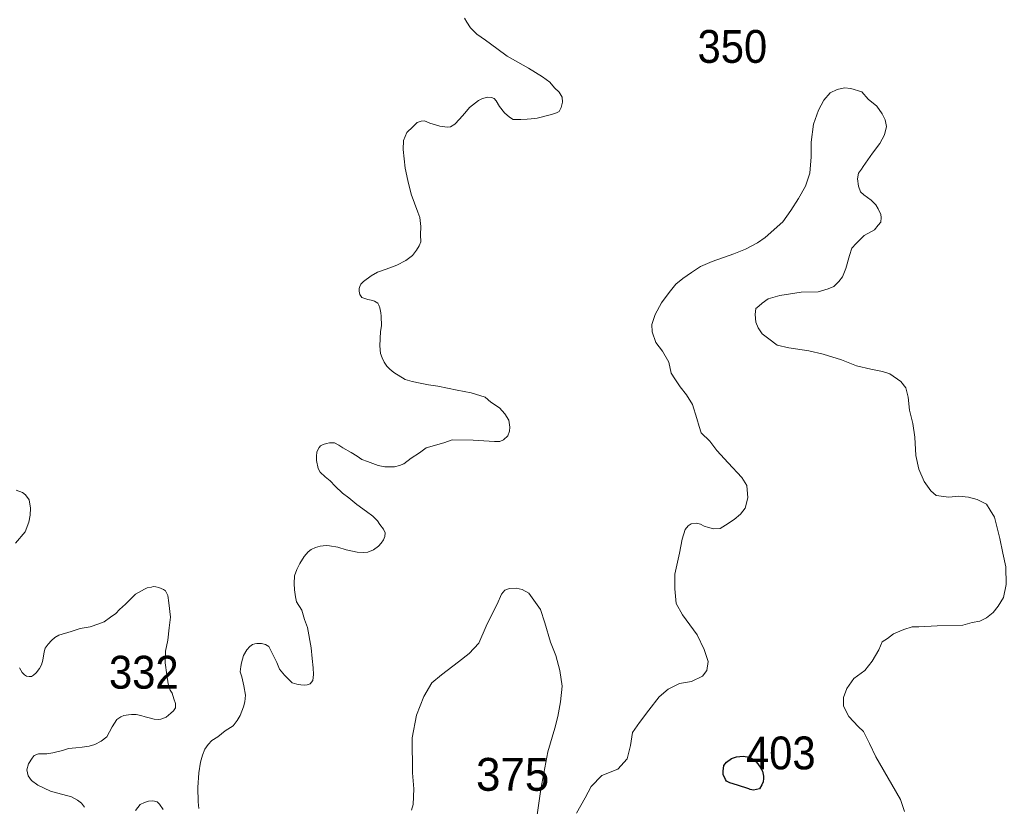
# Model space of a CAD drawing. Extents: x 445.4 to 500, y 8728.7 to 8784.
# Drawn here: x 477.878 to 482.683, y 8738.808 to 8742.638 of the extents above; entities that cross this region are included whole.
import ezdxf

# ---------------------------------------------------------------- set-up
doc = ezdxf.new("R2010")
doc.units = 0
doc.header["$LTSCALE"] = 0.064
doc.layers.add('1', color=7, linetype='Continuous', lineweight=25)
doc.layers.add('2', color=7, linetype='Continuous', lineweight=13)
doc.layers.add('21', color=7, linetype='Continuous')

msp = doc.modelspace()

# ---------------------------------------------------------------- linework, layer by layer
at = {"layer": '1'}
msp.add_lwpolyline([(481.4291, 8738.8939), (481.3733, 8738.9113), (481.3373, 8738.9218), (481.321, 8738.9311), (481.3152, 8738.938), (481.3035, 8738.9624), (481.3035, 8738.9798), (481.3082, 8739.0065), (481.3198, 8739.0239), (481.3454, 8739.0413), (481.3687, 8739.0494), (481.4012, 8739.0529), (481.4326, 8739.0471), (481.4501, 8739.0378), (481.4629, 8739.0262), (481.4733, 8739.0146), (481.4884, 8738.9937), (481.4966, 8738.9786), (481.5012, 8738.9543), (481.5001, 8738.9438), (481.4989, 8738.9276), (481.4931, 8738.9136), (481.4815, 8738.8939), (481.4664, 8738.8893), (481.4524, 8738.887), (481.435, 8738.8893)], close=True, dxfattribs=at)
at = {"layer": '2'}
for points in [[(480.0452, 8742.6452), (480.0558, 8742.6256), (480.0739, 8742.5985), (480.1042, 8742.5683), (480.1465, 8742.5381), (480.2024, 8742.4974), (480.2523, 8742.4612), (480.3568, 8742.4029), (480.4248, 8742.3592), (480.4596, 8742.3336), (480.4823, 8742.3064), (480.5049, 8742.2853), (480.52, 8742.2612), (480.5215, 8742.237), (480.5155, 8742.2099), (480.5049, 8742.1918), (480.4928, 8742.1842), (480.4687, 8742.1767)], [(481.0917, 8739.4061), (481.1496, 8739.4163), (481.2044, 8739.4419), (481.2249, 8739.4691), (481.2317, 8739.5133), (481.2112, 8739.571), (481.1772, 8739.6424), (481.1057, 8739.741), (481.075, 8739.7954), (481.0682, 8739.8667), (481.0682, 8739.9381), (481.092, 8740.0401), (481.1054, 8740.1093), (481.1189, 8740.1554), (481.1343, 8740.1746), (481.1478, 8740.1842), (481.1728, 8740.1861), (481.1939, 8740.1823), (481.2113, 8740.1727), (481.2324, 8740.165), (481.2594, 8740.1592), (481.2901, 8740.1611), (481.3152, 8740.1765), (481.3575, 8740.2053), (481.3883, 8740.2303), (481.4114, 8740.2591), (481.4248, 8740.3109), (481.419, 8740.3705), (481.396, 8740.4089), (481.3286, 8740.4799), (481.2728, 8740.5414), (481.2401, 8740.5855), (481.1975, 8740.627), (481.1871, 8740.6568), (481.1753, 8740.6967), (481.1542, 8740.7647), (481.126, 8740.8116), (481.0954, 8740.8514), (481.0696, 8740.8889), (481.0508, 8740.9171), (481.0391, 8740.971), (481.0085, 8741.0245), (480.9756, 8741.0667), (480.9591, 8741.1183), (480.9568, 8741.1534), (480.9732, 8741.2027), (481.0038, 8741.259), (481.0414, 8741.3105), (481.0743, 8741.3504), (481.1072, 8741.3785), (481.1494, 8741.4067), (481.1941, 8741.4372), (481.2505, 8741.4606), (481.3562, 8741.4981), (481.4125, 8741.5216), (481.4713, 8741.552), (481.5089, 8741.5778), (481.5942, 8741.6546), (481.6341, 8741.7085), (481.6717, 8741.7671), (481.7046, 8741.8281), (481.7257, 8741.8914), (481.7328, 8741.9711), (481.7328, 8742.0414), (481.745, 8742.1298), (481.7685, 8742.1978), (481.7943, 8742.2471), (481.8248, 8742.2822), (481.8601, 8742.2986), (481.8953, 8742.3057), (481.9259, 8742.3033), (481.9799, 8742.2869), (482.0104, 8742.2517), (482.0527, 8742.2166), (482.0786, 8742.1791), (482.0926, 8742.1509), (482.0997, 8742.1181), (482.0903, 8742.0782), (482.0668, 8742.036), (482.0316, 8741.9891), (481.9869, 8741.9235), (481.9776, 8741.9103), (481.9635, 8741.8916), (481.9588, 8741.8635), (481.9635, 8741.8283), (481.9729, 8741.8001), (481.9893, 8741.7861), (482.0246, 8741.7603), (482.0481, 8741.7368), (482.0598, 8741.7181), (482.0716, 8741.6899), (482.0739, 8741.6759), (482.0716, 8741.6524), (482.0598, 8741.6384), (482.041, 8741.6149), (481.9917, 8741.5868), (481.9517, 8741.5493), (481.9306, 8741.5258), (481.9189, 8741.4906), (481.9024, 8741.426), (481.886, 8741.3861)], [(480.4687, 8742.1767), (480.3988, 8742.1595), (480.37, 8742.155), (480.3504, 8742.1535), (480.3187, 8742.152), (480.2809, 8742.152), (480.2643, 8742.164), (480.2386, 8742.1851), (480.2144, 8742.2153), (480.1993, 8742.2424), (480.1887, 8742.2545), (480.1766, 8742.259), (480.1585, 8742.2605), (480.1328, 8742.2545), (480.1132, 8742.244), (480.0693, 8742.2108), (480.0467, 8742.1836), (480.0195, 8742.1535), (479.9968, 8742.1293), (479.9756, 8742.1173), (479.9605, 8742.1142), (479.9243, 8742.1203), (479.8759, 8742.1339), (479.8502, 8742.1459), (479.8336, 8742.1444), (479.814, 8742.1384), (479.7928, 8742.1173), (479.7641, 8742.0886), (479.7475, 8742.0494), (479.746, 8742.0057), (479.7548, 8741.9161), (479.7684, 8741.8558), (479.785, 8741.7894), (479.818, 8741.7013), (479.8263, 8741.6745), (479.8312, 8741.6316), (479.83, 8741.59), (479.8312, 8741.5569), (479.8239, 8741.5373), (479.8104, 8741.5165), (479.7907, 8741.4908), (479.7588, 8741.4651), (479.7147, 8741.4431), (479.6628, 8741.4238), (479.6211, 8741.4092), (479.5892, 8741.3908), (479.5524, 8741.3639), (479.5389, 8741.3504), (479.5353, 8741.3397), (479.5311, 8741.3288), (479.5311, 8741.317), (479.5344, 8741.2994), (479.5453, 8741.286), (479.5537, 8741.2818), (479.5731, 8741.2759), (479.5899, 8741.2734), (479.6067, 8741.2684), (479.6151, 8741.2634), (479.6218, 8741.2575), (479.6268, 8741.2483), (479.6319, 8741.2357), (479.6369, 8741.2114), (479.6394, 8741.1946), (479.6409, 8741.1477), (479.6362, 8741.1194), (479.6327, 8741.0508), (479.635, 8741.013), (479.6433, 8740.9917), (479.654, 8740.9704), (479.6658, 8740.9515), (479.6812, 8740.9373), (479.7002, 8740.9208), (479.7549, 8740.887), (479.7892, 8740.8764), (479.8283, 8740.8681), (479.8698, 8740.861), (479.9148, 8740.8539), (479.961, 8740.8445), (480.0083, 8740.835), (480.0774, 8740.8207), (480.1449, 8740.8007), (480.1722, 8740.7752), (480.2142, 8740.7479), (480.2415, 8740.7187), (480.2598, 8740.6878), (480.2653, 8740.655), (480.2634, 8740.635), (480.2561, 8740.6113), (480.2343, 8740.5931), (480.216, 8740.584), (480.1905, 8740.584), (480.0865, 8740.5913), (479.9844, 8740.5931), (479.9442, 8740.5786), (479.8585, 8740.5531), (479.8257, 8740.5294), (479.7855, 8740.5039), (479.749, 8740.4761), (479.7285, 8740.4679), (479.7029, 8740.4617), (479.6803, 8740.4607)], [(481.886, 8741.3861), (481.8672, 8741.3627), (481.8437, 8741.3392), (481.8155, 8741.3275), (481.7662, 8741.3134), (481.6839, 8741.3111), (481.5806, 8741.2947), (481.5242, 8741.2783), (481.4936, 8741.2572), (481.4772, 8741.2431), (481.4631, 8741.2314), (481.4608, 8741.2032), (481.4631, 8741.1657), (481.4749, 8741.1376), (481.4936, 8741.1094), (481.5265, 8741.0837), (481.5665, 8741.0532), (481.6248, 8741.04), (481.7211, 8741.0259), (481.7916, 8741.0095), (481.8809, 8740.9814), (481.9537, 8740.9532), (482.0242, 8740.9368), (482.0806, 8740.9251), (482.1158, 8740.9134), (482.1698, 8740.8759), (482.1933, 8740.8454), (482.2051, 8740.8008), (482.2121, 8740.7375), (482.2286, 8740.6719), (482.238, 8740.6062), (482.2433, 8740.5156), (482.2574, 8740.4499), (482.2833, 8740.389), (482.3161, 8740.3444), (482.342, 8740.321), (482.4031, 8740.3139), (482.4524, 8740.3186), (482.4994, 8740.3139), (482.5417, 8740.3022), (482.5863, 8740.2788), (482.6051, 8740.2506), (482.6262, 8740.2155), (482.6521, 8740.1123), (482.6666, 8740.0403), (482.6807, 8739.9747), (482.6831, 8739.8879), (482.669, 8739.8246), (482.6431, 8739.7824), (482.6196, 8739.7519), (482.5868, 8739.7262), (482.5539, 8739.7097), (482.5163, 8739.7027), (482.4716, 8739.691), (482.3471, 8739.6863), (482.2579, 8739.6816), (482.225, 8739.6816), (482.185, 8739.6699), (482.1334, 8739.6488), (482.1052, 8739.6253), (482.0793, 8739.6089), (482.0622, 8739.5696), (482.0293, 8739.5156), (481.994, 8739.4687), (481.94, 8739.4312), (481.9071, 8739.382), (481.8907, 8739.3374), (481.8907, 8739.2952), (481.9165, 8739.246), (481.9612, 8739.1968), (481.987, 8739.1733), (482.0175, 8739.1147), (482.0481, 8739.049), (482.1259, 8738.9139), (482.1682, 8738.8412), (482.187, 8738.7826)], [(479.6803, 8740.4607), (479.6567, 8740.4617), (479.6239, 8740.4679), (479.5716, 8740.4863), (479.5449, 8740.4976), (479.5214, 8740.5129), (479.4926, 8740.5303), (479.4516, 8740.5529), (479.4331, 8740.5672), (479.4106, 8740.5774), (479.387, 8740.5774), (479.3726, 8740.5744), (479.3562, 8740.5703), (479.3439, 8740.5631), (479.3367, 8740.5549), (479.3296, 8740.5447), (479.3254, 8740.5324), (479.3234, 8740.5129), (479.3244, 8740.4925), (479.3316, 8740.4536), (479.3419, 8740.4351), (479.3654, 8740.4126), (479.3901, 8740.3932), (479.4146, 8740.3669), (479.4505, 8740.3331), (479.4813, 8740.3095), (479.5203, 8740.2778), (479.5669, 8740.2434), (479.598, 8740.221), (479.6204, 8740.1986), (479.6324, 8740.1797), (479.6497, 8740.1573), (479.6583, 8740.1401), (479.6566, 8740.1212), (479.6497, 8740.1057), (479.6393, 8740.0902), (479.6255, 8740.0748), (479.6014, 8740.0575), (479.5738, 8740.0455), (479.5514, 8740.0438), (479.5221, 8740.0455), (479.4687, 8740.0575), (479.4273, 8740.0696), (479.3876, 8740.0765), (479.3704, 8740.0782), (479.3411, 8740.0748), (479.3187, 8740.0679), (479.298, 8740.0593), (479.2825, 8740.0472), (479.2635, 8740.0249), (479.2428, 8739.9904), (479.2273, 8739.9612), (479.217, 8739.9302), (479.2152, 8739.8924), (479.2166, 8739.8624), (479.2217, 8739.828), (479.2269, 8739.8039), (479.2528, 8739.7626), (479.2648, 8739.7178), (479.2803, 8739.6783), (479.2976, 8739.5795), (479.3028, 8739.5279), (479.308, 8739.4831), (479.3096, 8739.45), (479.3061, 8739.4207), (479.2923, 8739.4052), (479.2785, 8739.4001), (479.2647, 8739.3984), (479.2475, 8739.4001), (479.2285, 8739.4035), (479.2044, 8739.4087), (479.1682, 8739.4465), (479.1441, 8739.4758), (479.1303, 8739.5085), (479.0923, 8739.5859), (479.0751, 8739.5962), (479.0561, 8739.6014), (479.0337, 8739.6014), (479.0234, 8739.5997), (479.0113, 8739.5962), (478.9993, 8739.5859), (478.9837, 8739.5704), (478.9682, 8739.5429), (478.9579, 8739.5068), (478.9544, 8739.4896), (478.9527, 8739.4637), (478.9596, 8739.4379), (478.9699, 8739.3949), (478.9786, 8739.3502), (478.9751, 8739.3175), (478.9682, 8739.2934), (478.9524, 8739.2497), (478.9369, 8739.2256), (478.918, 8739.1998), (478.8783, 8739.1757), (478.8438, 8739.1465), (478.8145, 8739.1293), (478.7953, 8739.1095), (478.7798, 8739.0871), (478.7677, 8739.0579), (478.7591, 8739.0235)], [(477.8573, 8740.0899), (477.9046, 8740.1447), (477.9226, 8740.1919), (477.9294, 8740.2256), (477.9316, 8740.2594), (477.9249, 8740.2998), (477.9068, 8740.3245), (477.8911, 8740.3358), (477.8618, 8740.347)], [(478.6365, 8739.309), (478.6293, 8739.3319), (478.6207, 8739.3591), (478.6106, 8739.3735), (478.6009, 8739.4045), (478.595, 8739.4477), (478.5872, 8739.5066), (478.5891, 8739.5635), (478.599, 8739.6165), (478.6068, 8739.6774), (478.6127, 8739.7284), (478.6049, 8739.7991), (478.5989, 8739.834), (478.5932, 8739.8482), (478.5882, 8739.8574), (478.579, 8739.8638), (478.5669, 8739.8694), (478.5555, 8739.8744), (478.5413, 8739.8765), (478.5279, 8739.8779), (478.5193, 8739.8758), (478.4995, 8739.8715), (478.4867, 8739.8659), (478.4427, 8739.8411), (478.4221, 8739.8212), (478.3937, 8739.7922), (478.3646, 8739.7667), (478.3461, 8739.7475), (478.3198, 8739.7298), (478.2893, 8739.7057), (478.2639, 8739.6966), (478.2208, 8739.6829), (478.1729, 8739.6747), (478.129, 8739.6601), (478.0696, 8739.6423), (478.0501, 8739.6309), (478.0338, 8739.6155), (478.0167, 8739.5984), (478.0029, 8739.579), (477.998, 8739.5611), (477.9915, 8739.5205), (477.985, 8739.4978), (477.9743, 8739.4786), (477.958, 8739.4583), (477.945, 8739.4462), (477.936, 8739.4405), (477.9239, 8739.4405), (477.9117, 8739.4413), (477.9011, 8739.4478), (477.8905, 8739.4592), (477.8775, 8739.4827)], [(479.787, 8738.7891), (479.7939, 8738.8167), (479.7985, 8738.8928), (479.7916, 8738.9711), (479.7904, 8739.1417), (479.8101, 8739.252), (479.8457, 8739.3426), (479.8852, 8739.4096), (479.9325, 8739.449), (480.0154, 8739.5121), (480.0668, 8739.5515), (480.1141, 8739.6027), (480.1497, 8739.6855), (480.1787, 8739.7457), (480.2033, 8739.7928), (480.2241, 8739.8419), (480.2411, 8739.8607), (480.2638, 8739.8683), (480.2959, 8739.8701), (480.3261, 8739.8645), (480.3583, 8739.8456), (480.3828, 8739.8117), (480.415, 8739.7664), (480.4357, 8739.7023), (480.4641, 8739.608), (480.4887, 8739.542), (480.5094, 8739.4703), (480.5209, 8739.394), (480.5115, 8739.3167), (480.4983, 8739.245), (480.485, 8739.1884), (480.4502, 8739.0741), (480.4156, 8738.8911), (480.381, 8738.6426)], [(480.5906, 8738.7754), (480.6315, 8738.8502), (480.6621, 8738.9046), (480.7132, 8738.9589), (480.7915, 8738.9895), (480.8363, 8739.039), (480.8533, 8739.1036), (480.8635, 8739.1682), (480.8976, 8739.2158), (480.9419, 8739.277), (480.9929, 8739.3415), (481.0372, 8739.3789), (481.0917, 8739.4061)], [(478.1931, 8738.804), (478.1793, 8738.8229), (478.1592, 8738.8384), (478.1297, 8738.8541), (478.0884, 8738.8659), (478.0569, 8738.8737), (478.0274, 8738.8816), (477.9979, 8738.8973), (477.9665, 8738.911), (477.935, 8738.9346), (477.9193, 8738.9562), (477.9134, 8738.9856), (477.9213, 8739.0151), (477.939, 8739.0425), (477.9488, 8739.0563), (477.9704, 8739.0641), (478.0097, 8739.0641), (478.0392, 8739.068), (478.0864, 8739.0798), (478.1159, 8739.0896), (478.1513, 8739.0936), (478.1828, 8739.0955), (478.2162, 8739.1014), (478.2437, 8739.1093), (478.2752, 8739.125), (478.3027, 8739.1465), (478.3283, 8739.1956), (478.3508, 8739.2302), (478.3709, 8739.2431), (478.3853, 8739.2503), (478.4082, 8739.2531), (478.4226, 8739.256), (478.4455, 8739.256), (478.4685, 8739.2503), (478.49, 8739.2445), (478.5159, 8739.2374), (478.5331, 8739.2331), (478.5518, 8739.2316), (478.5661, 8739.2331), (478.592, 8739.2417), (478.6149, 8739.2617), (478.6278, 8739.2732), (478.6365, 8739.2875), (478.6365, 8739.309)], [(478.7591, 8739.0235), (478.7505, 8738.9718), (478.7453, 8738.8996), (478.747, 8738.8307), (478.7505, 8738.797)], [(478.5764, 8738.7935), (478.5591, 8738.8194), (478.5471, 8738.8297), (478.535, 8738.8331), (478.5246, 8738.8348), (478.5057, 8738.8331), (478.4867, 8738.8262), (478.4643, 8738.8176), (478.4419, 8738.7884)]]:
    msp.add_lwpolyline(points, dxfattribs=at)

# ---------------------------------------------------------------- texts
at = {"layer": '21', "width": 0.95}
for s, p in [('350', (481.1795, 8742.428)), ('332', (478.313, 8739.381)), ('403', (481.4154, 8738.9881))]:
    msp.add_text(s, height=0.16, dxfattribs=at).set_placement(p)
at = {"layer": '21'}
msp.add_text('375', height=0.16, dxfattribs=at).set_placement((480.1006, 8738.8838))

doc.saveas('drawing.dxf')
